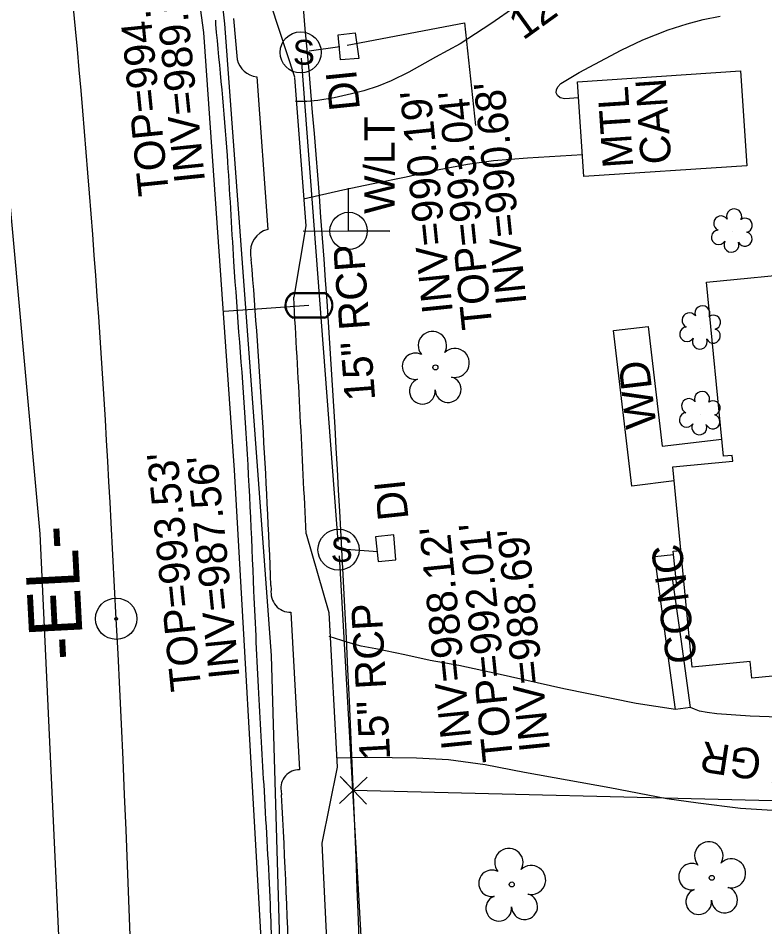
# Model space of a CAD drawing. Extents: x 1614611 to 1617571, y 898867 to 905462.
# Drawn here: x 1616674.8 to 1616772.7, y 902317.5 to 902436.7 of the extents above; entities that cross this region are included whole.
import ezdxf

# ---------------------------------------------------------------- set-up
doc = ezdxf.new("R2010")
doc.units = 0
for name, color, linetype in [('Exist Boundary Watershed Residential C 05', 7, 'Continuous'), ('Exist Building', 7, 'Continuous'), ('Exist Building Metal Canopy', 7, 'Continuous'), ('Exist Building Text', 7, 'Continuous'), ('Exist Horizontal Alignment Tick Label', 7, 'Continuous'), ('Exist Other Culture Area Outline', 7, 'Continuous'), ('Exist Roads Soil', 7, 'Continuous'), ('Exist Roads Soil Text', 7, 'Continuous'), ('Exist Structure Minor Drop Inlet Top Elevation', 7, 'Continuous'), ('Exist Structure Minor Pipes RCP 15 Inch Invert', 7, 'Continuous'), ('Exist Structure Minor Storm Sewer Manhole Top Elevation', 7, 'Continuous'), ('Exist Survey Centerline Point CELL', 7, 'Continuous'), ('Exist Utilities Power Joint Use Telephone CELL', 7, 'Continuous'), ('Exist Utilities Power Joint Use Telephone Text', 7, 'Continuous'), ('Exist Utilities Telephone UG Cable SUE LOS B', 7, 'Continuous'), ('Exist Utilities Telephone UG FO SUE LOS B', 7, 'Continuous'), ('Exist Utilities Water UG Line SUE LOS B', 7, 'Continuous'), ('Exist Vegetation Shrub CELL', 7, 'Continuous'), ('Exist Vegetation Tree CELL', 7, 'Continuous'), ('Prop Drainage Structure Catch Basin Adjust CELL', 7, 'Continuous'), ('Prop Drainage Structure Catch Basin Adjust Label', 7, 'Continuous'), ('Prop Drainage Structure Pipe Alternate 30in Label', 7, 'Continuous'), ('Prop Drainage Structure Pipe RCP 15in Class IV', 7, 'Continuous'), ('Prop Drainage Structure Tops and Inverts LABEL', 7, 'Continuous'), ('Prop Earthen Structure Head Ditch Label', 7, 'Continuous'), ('Prop Erosion Embankment Toe Protection CELL', 7, 'Continuous'), ('Prop Erosion Embankment Toe Protection with Rip Rap 2 Detail CELL', 7, 'Continuous'), ('Prop Plan Preparation Table Ditch Data CELL', 7, 'Continuous'), ('Prop SS Transition Line', 7, 'Continuous'), ('Raster_Level_2', 7, 'Continuous'), ('Raster_Level_3', 7, 'Continuous'), ('Scratch_Level_1', 7, 'Continuous'), ('Scratch_Level_9', 7, 'Continuous')]:
    doc.layers.add(name, color=color, linetype=linetype)

# ---------------------------------------------------------------- blocks, each defined once
blk = doc.blocks.new('EXIST STRUCTURE MINOR STORM SEWER MANHOLE')
at = {"layer": 'Prop Drainage Structure Pipe RCP 15in Class IV'}
blk.add_circle((0, 0), 0.0539, dxfattribs=at)
blk.add_text('S', height=0.065, dxfattribs=at).set_placement((-0.0206, -0.032))
blk = doc.blocks.new('EXIST SURVEY CENTERLINE POINT')
at = {"layer": 'Exist Survey Centerline Point CELL'}
for radius in [0.0542, 0.00375]:
    blk.add_circle((0, 0), radius, dxfattribs=at)
blk = doc.blocks.new('EXIST UTILITIES WATER METER')
at = {"layer": 'Prop SS Transition Line'}
blk.add_line((0, 0), (0, 0), dxfattribs=at)
for points in [[(-0.0408, 0.034), (0.0408, 0.034)], [(-0.0408, 0.0312), (0.0408, 0.0312)], [(0.0408, -0.0312), (-0.0413, -0.0312)], [(0.0408, -0.034), (-0.0413, -0.034)]]:
    blk.add_lwpolyline(points, dxfattribs=at)
for centre, radius, start, end in [((-0.0261, -0.0001), 0.0371, 113.178, 245.9794), ((-0.0259, -0.0001), 0.0347, 115.3009, 243.7824), ((0.0259, 0), 0.0371, 293.6483, 66.3084), ((0.0261, 0), 0.0345, 295.1272, 64.8728)]:
    blk.add_arc(centre, radius, start, end, dxfattribs=at)

msp = doc.modelspace()

# ---------------------------------------------------------------- linework, layer by layer
at = {"layer": 'Exist Boundary Watershed Residential C 05'}
for p, q in [((1616703.02, 902436.7), (1616703.51, 902431.31)), ((1616706.07, 902429.04), (1616707.51, 902409.02)), ((1616705.26, 902405.59), (1616705.35, 902405.07)), ((1616707.94, 902362.29), (1616707.97, 902361.76)), ((1616710.56, 902358.78), (1616711.7, 902338.11)), ((1616709.26, 902335.35), (1616709.32, 902334.83))]:
    msp.add_line(p, q, dxfattribs=at)
for centre, major_axis, ratio, start_param, end_param in [((1616706.37, 902431.96), (1.8, -2.32), 0.998961, 4.276319, 5.52203), ((1616708.3, 902406.05), (-2.36, -1.96), 0.999574, 4.277693, 5.74022), ((1615768.72, 902322.44), (-16.72, 991.07), 0.94837, 4.736603, 4.779853), ((1616710.53, 902361.37), (-2.59, -0.03), 0.999169, 6.117366, 7.854895), ((1616711.61, 902335.73), (-0.28, 2.37), 0.99892, 6.126992, 7.894157), ((1615570.16, 902271.61), (318.56, 1096.57), 0.999023, 5.027905, 5.050255)]:
    msp.add_ellipse(centre, major_axis=major_axis, ratio=ratio, start_param=start_param, end_param=end_param, dxfattribs=at)
at = {"layer": 'Exist Building'}
msp.add_lwpolyline([(1616804.86, 902353.42), (1616771, 902350.14), (1616770.79, 902352.34), (1616763.17, 902351.6), (1616760.63, 902377.86), (1616768.51, 902378.62), (1616768.43, 902379.37), (1616767.27, 902379.26), (1616765.05, 902402.11), (1616791.89, 902404.71), (1616793.95, 902383.49), (1616801.8, 902384.25), (1616801.98, 902382.41), (1616804.86, 902382.69), (1616807.23, 902358.2), (1616804.42, 902357.93)], close=True, dxfattribs=at)
at = {"layer": 'Exist Building Metal Canopy'}
msp.add_lwpolyline([(1616770.33, 902417.36), (1616748.96, 902415.94), (1616748.13, 902428.39), (1616769.49, 902429.82)], close=True, dxfattribs=at)
at = {"layer": 'Exist Other Culture Area Outline'}
for points in [[(1616760.8, 902376.01), (1616755.27, 902375.35), (1616752.85, 902395.74), (1616757.38, 902396.28), (1616759.25, 902380.58), (1616767.05, 902381.51)], [(1616762.09, 902362.73), (1616761.09, 902362.63), (1616760.66, 902366.81), (1616761.69, 902366.91)], [(1616762.96, 902346.3), (1616760.99, 902346.03), (1616759.76, 902354.99), (1616758.26, 902366.1), (1616760.71, 902366.38)], [(1616762.96, 902346.3), (1616761.73, 902355.26), (1616760.6, 902363.25), (1616761.03, 902363.3)]]:
    msp.add_lwpolyline(points, dxfattribs=at)
at = {"layer": 'Exist Roads Soil'}
for points in [[(1616740.04, 902438.27), (1616736.78, 902435.97), (1616732.75, 902433.37), (1616729.53, 902431.61), (1616726.01, 902429.65), (1616723.71, 902428.5), (1616721.99, 902427.79), (1616720.13, 902427.2), (1616718.5, 902426.78), (1616716.24, 902426.26), (1616714.08, 902425.92), (1616712.64, 902425.8), (1616711.16, 902425.81)], [(1616748.27, 902426.26), (1616746.49, 902426.15), (1616745.85, 902426.28), (1616745.5, 902426.57), (1616745.35, 902426.93), (1616745.36, 902427.33), (1616745.53, 902427.7), (1616745.94, 902428.14), (1616748.37, 902429.59), (1616753.87, 902432.51), (1616756.7, 902433.89), (1616760, 902435.21), (1616762.5, 902436), (1616764.6, 902436.55), (1616766.85, 902436.99)], [(1616712.2, 902413.04), (1616717.37, 902414.22), (1616721.34, 902415.04), (1616725.66, 902415.9), (1616729.29, 902416.73), (1616733.69, 902417.58), (1616737.11, 902418.06), (1616741.59, 902418.41), (1616748.77, 902418.82)], [(1616760.99, 902346.03), (1616755.84, 902346.82), (1616746.33, 902348.75), (1616737.61, 902350.7), (1616732.59, 902351.81), (1616728.83, 902352.48), (1616725.47, 902353.21), (1616721.68, 902353.97), (1616719.78, 902354.36), (1616718.07, 902354.83), (1616715.56, 902355.62)], [(1616776.96, 902344.94), (1616770.75, 902345.16), (1616766.39, 902345.45), (1616765.12, 902345.63), (1616764.14, 902345.83), (1616763.48, 902346.07), (1616762.96, 902346.3)], [(1616716.51, 902339.71), (1616720.63, 902339.78), (1616727, 902339.71), (1616731.2, 902339.48), (1616736.04, 902338.81), (1616741.16, 902337.82), (1616752.36, 902335.79), (1616759.83, 902334.37), (1616763.96, 902333.8), (1616769.5, 902333.1), (1616775.11, 902332.75)]]:
    msp.add_lwpolyline(points, dxfattribs=at)
at = {"layer": 'Exist Utilities Power Joint Use Telephone CELL'}
msp.add_line((1616718.12, 902408.81), (1616718.12, 902408.81), dxfattribs=at)
msp.add_lwpolyline([(1616712.18, 902408.81), (1616723.52, 902408.77), (1616718.12, 902408.79), (1616718.12, 902414.43)], dxfattribs=at)
msp.add_circle((1616718.12, 902408.81), 2.45, dxfattribs=at)
at = {"layer": 'Exist Utilities Telephone UG Cable SUE LOS B'}
msp.add_lwpolyline([(1616656.18, 902051.21), (1616671.87, 902049.35), (1616673.37, 902060.47), (1616677.62, 902099.17), (1616679.56, 902131), (1616682.04, 902274.91), (1616677.66, 902369.06), (1616673.54, 902414.87), (1616672.97, 902415.98), (1616670.64, 902416.97), (1616666.17, 902416.66), (1616663.13, 902416.28), (1616653.85, 902415.38)], dxfattribs=at)
at = {"layer": 'Exist Utilities Telephone UG FO SUE LOS B'}
msp.add_lwpolyline([(1616708.77, 902097.06), (1616709.58, 902140.25), (1616710.58, 902218.49), (1616710.01, 902283.99), (1616708.01, 902353.12), (1616701.91, 902435.97), (1616696.63, 902483.57), (1616691.69, 902526.33), (1616686.21, 902567.93), (1616679.63, 902610.92), (1616669.49, 902655.34), (1616656.06, 902717.52), (1616648.63, 902743.65), (1616630.5, 902815.16), (1616628.69, 902826.2), (1616634.94, 902830.28)], dxfattribs=at)
at = {"layer": 'Exist Utilities Water UG Line SUE LOS B'}
msp.add_line((1616712.92, 902399.05), (1616701.8, 902398.26), dxfattribs=at)
msp.add_lwpolyline([(1616682.85, 901889.35), (1616688.26, 901932.45), (1616696.61, 902016.19), (1616699.26, 902055.42), (1616702.78, 902110.39), (1616705.34, 902181.72), (1616707.31, 902255.35), (1616706.62, 902316.75), (1616703.14, 902377.45), (1616699.12, 902434.84), (1616686.86, 902524.85), (1616669.78, 902622.34), (1616658.13, 902681.62), (1616634.87, 902784.56), (1616617.17, 902853.52), (1616602.15, 902900.61), (1616584.28, 902954.24), (1616571.86, 902993.81)], dxfattribs=at)
at = {"layer": 'Exist Vegetation Shrub CELL'}
for p, q in [((1616768.44, 902408.68), (1616768.44, 902408.68)), ((1616764.29, 902395.96), (1616764.29, 902395.96)), ((1616764.23, 902384.72), (1616764.23, 902384.72))]:
    msp.add_line(p, q, dxfattribs=at)
for centre, radius, start, end in [((1616766.96, 902409.81), 0.968, 35.8908, 245.4216), ((1616768.67, 902410.72), 0.99, 334.8391, 200.4717), ((1616770.12, 902409.55), 0.929, 284.4567, 126.0861), ((1616766.64, 902407.98), 0.955, 95.1099, 327.9534), ((1616770.08, 902407.75), 0.937, 204.9913, 73.4601), ((1616768.32, 902407), 0.984, 151.2797, 21.387), ((1616764.51, 902398), 0.99, 334.8391, 200.4717), ((1616762.8, 902397.09), 0.968, 35.8908, 245.4216), ((1616765.96, 902396.83), 0.929, 284.4567, 126.0861), ((1616762.49, 902395.26), 0.955, 95.1099, 327.9534), ((1616765.92, 902395.03), 0.937, 204.9913, 73.4601), ((1616764.16, 902394.28), 0.984, 151.2797, 21.387), ((1616762.75, 902385.85), 0.968, 35.8908, 245.4216), ((1616764.46, 902386.76), 0.99, 334.8391, 200.4717), ((1616765.9, 902385.59), 0.929, 284.4567, 126.0861), ((1616762.43, 902384.02), 0.955, 95.1099, 327.9534), ((1616765.87, 902383.79), 0.937, 204.9913, 73.4601), ((1616764.1, 902383.04), 0.984, 151.2797, 21.387)]:
    msp.add_arc(centre, radius, start, end, dxfattribs=at)
at = {"layer": 'Exist Vegetation Tree CELL'}
for p, q in [((1616729.5, 902390.91), (1616729.5, 902390.91)), ((1616765.73, 902323.95), (1616765.73, 902323.95)), ((1616739.51, 902323.08), (1616739.51, 902323.08))]:
    msp.add_line(p, q, dxfattribs=at)
for centre in [(1616729.5, 902390.91), (1616765.73, 902323.95), (1616739.51, 902323.08)]:
    msp.add_circle(centre, 0.326, dxfattribs=at)
for centre, radius, start, end in [((1616729.11, 902393.78), 1.86, 330.1651, 219.7134), ((1616726.89, 902391.06), 1.73, 62.6636, 279.3457), ((1616732.05, 902391.5), 1.9, 257.1011, 134.1999), ((1616727.79, 902387.79), 1.69, 111.5671, 6.231), ((1616731.17, 902388.01), 1.7, 181.2822, 74.56), ((1616765.35, 902326.82), 1.86, 330.1651, 219.7134), ((1616739.13, 902325.95), 1.86, 330.1651, 219.7134), ((1616768.28, 902324.54), 1.9, 257.1011, 134.1999), ((1616736.91, 902323.23), 1.73, 62.6636, 279.3457), ((1616742.06, 902323.67), 1.9, 257.1011, 134.1999), ((1616763.13, 902324.1), 1.73, 62.6636, 279.3457), ((1616764.03, 902320.83), 1.69, 111.5671, 6.231), ((1616767.41, 902321.05), 1.7, 181.2822, 74.56), ((1616737.81, 902319.96), 1.69, 111.5671, 6.231), ((1616741.19, 902320.18), 1.7, 181.2822, 74.56)]:
    msp.add_arc(centre, radius, start, end, dxfattribs=at)
at = {"layer": 'Prop Drainage Structure Pipe Alternate 30in Label'}
msp.add_line((1616718.75, 902335.44), (1616926.32, 902330.37), dxfattribs=at)
at = {"layer": 'Prop Drainage Structure Tops and Inverts LABEL'}
msp.add_line((1616718.75, 902335.44), (1616718.75, 902335.44), dxfattribs=at)
msp.add_lwpolyline([(1616716.94, 902333.72), (1616720.56, 902337.17), (1616718.75, 902335.44), (1616717.02, 902337.25), (1616720.47, 902333.63)], dxfattribs=at)
at = {"layer": 'Prop Earthen Structure Head Ditch Label'}
msp.add_line((1616717.61, 902359.5), (1616716.96, 902372.07), dxfattribs=at)
for centre, radius, start, end in [((1615052.19, 902285.31), 1667.02, 2.98333, 9.05), ((1614235.45, 902230.14), 2485.53, 356.91518, 2.98333)]:
    msp.add_arc(centre, radius, start, end, dxfattribs=at)
at = {"layer": 'Prop Erosion Embankment Toe Protection CELL'}
for points in [[(1616716.73, 902434.55), (1616718.99, 902434.78), (1616719.45, 902431.44), (1616717.06, 902431.24), (1616716.73, 902434.55)], [(1616722, 902365.43), (1616724.3, 902365.68), (1616724.04, 902368.96), (1616721.65, 902368.69), (1616722, 902365.43)]]:
    msp.add_lwpolyline(points, dxfattribs=at)
at = {"layer": 'Prop Plan Preparation Table Ditch Data CELL'}
for p, q in [((1616712.95, 902432.45), (1616716.95, 902433)), ((1616711.91, 902431.48), (1616716.71, 902368.05)), ((1616717.79, 902367.07), (1616721.93, 902366.78)), ((1616716.87, 902366.19), (1616720.08, 902309.68))]:
    msp.add_line(p, q, dxfattribs=at)
at = {"layer": 'Raster_Level_2'}
msp.add_line((1616687.65, 902357.94), (1616687, 902370.51), dxfattribs=at)
for centre, radius, start, end in [((1615052.19, 902285.31), 1637.02, 2.98333, 9.05), ((1614235.45, 902230.14), 2455.53, 356.08333, 2.98333)]:
    msp.add_arc(centre, radius, start, end, dxfattribs=at)
at = {"layer": 'Raster_Level_3'}
msp.add_lwpolyline([(1616717.94, 902433.18), (1616733.3, 902436.1), (1616734.74, 902422.65)], dxfattribs=at)
at = {"layer": 'Scratch_Level_1'}
msp.add_line((1616707.92, 902438.46), (1616711.01, 902429.04), dxfattribs=at)
for points in [[(1616711.03, 902428.94), (1616712.5, 902409.5), (1616710.93, 902400.13)], [(1616712.55, 902369.06), (1616715.51, 902358.74), (1616716.6, 902338.47), (1616714.62, 902328.49), (1616715.21, 902315.8), (1616718.08, 902305.92), (1616718.43, 902285.38), (1616716.14, 902275.65)]]:
    msp.add_lwpolyline(points, dxfattribs=at)
msp.add_ellipse((1614231.79, 902241.59), major_axis=(-29.92, 2644.12), ratio=0.939305, start_param=4.749984, end_param=4.761751, dxfattribs=at)
at = {"layer": 'Scratch_Level_9'}
msp.add_line((1616700.67, 902436.46), (1616700.66, 902435.94), dxfattribs=at)
msp.add_spline([(1616700.66, 902435.94), (1616702.18, 902418.73), (1616703.04, 902404.79), (1616704.57, 902383.66), (1616705.67, 902361.58), (1616706.31, 902348.15), (1616707.03, 902335.33), (1616707.82, 902320.47), (1616708.2, 902308.47), (1616708.4, 902295.6), (1616708.73, 902282.72), (1616709.32, 902240.78), (1616708.76, 902198.62), (1616708, 902154.76), (1616706.39, 902118.44)], degree=3, dxfattribs=at)

# ---------------------------------------------------------------- block references
at = {"layer": 'Exist Horizontal Alignment Tick Label', "xscale": 50, "yscale": 50, "rotation": 1.7967031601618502e-12}
msp.add_blockref('EXIST SURVEY CENTERLINE POINT', (1616687.65, 902357.94), dxfattribs=at)
at = {"layer": 'Prop Drainage Structure Pipe RCP 15in Class IV', "xscale": 50, "yscale": 50}
for p in [(1616711.83, 902432.23), (1616716.8, 902367)]:
    msp.add_blockref('EXIST STRUCTURE MINOR STORM SEWER MANHOLE', p, dxfattribs=at)
at = {"layer": 'Prop SS Transition Line', "xscale": 50, "yscale": 50}
msp.add_blockref('EXIST UTILITIES WATER METER', (1616712.92, 902399.05), dxfattribs=at)

# ---------------------------------------------------------------- texts
at = {"layer": 'Exist Building Text'}
for s, rotation, p in [('CAN', 93.8148, (1616760.44, 902417.69)), ('MTL ', 93.8148, (1616755.45, 902417.2)), ('WD', 96.7806, (1616758.49, 902383.16)), ('CONC', 97.7191, (1616763.83, 902352.32))]:
    msp.add_text(s, height=4, rotation=rotation, dxfattribs=at).set_placement(p)
at = {"layer": 'Exist Roads Soil Text'}
for rotation, p in [(35.7973, (1616741, 902433.75)), (171.355, (1616780.83, 902339.4))]:
    msp.add_text("12' GR", height=4, rotation=rotation, dxfattribs=at).set_placement(p)
at = {"layer": 'Exist Structure Minor Drop Inlet Top Elevation'}
for s, p in [("TOP=993.04'", (1616736.98, 902396.08)), ("TOP=992.01'", (1616739.7, 902339.38))]:
    msp.add_text(s, height=4, rotation=95.8113, dxfattribs=at).set_placement(p)
at = {"layer": 'Exist Structure Minor Pipes RCP 15 Inch Invert'}
for s, p in [("INV=989.98'", (1616699.3, 902415.33)), ("INV=990.68'", (1616741.46, 902399.3)), ("INV=990.19'", (1616731.79, 902398.17)), ("INV=987.56'", (1616703.83, 902350.27)), ("INV=988.12'", (1616734.33, 902340.95)), ("INV=988.69'", (1616744.54, 902340.68))]:
    msp.add_text(s, height=4, rotation=95.8113, dxfattribs=at).set_placement(p)
at = {"layer": 'Exist Structure Minor Storm Sewer Manhole Top Elevation'}
for s, p in [("TOP=994.37'", (1616694.57, 902413.61)), ("TOP=993.53'", (1616698.82, 902348.62))]:
    msp.add_text(s, height=4, rotation=95.8113, dxfattribs=at).set_placement(p)
at = {"layer": 'Exist Utilities Power Joint Use Telephone Text'}
msp.add_text('W/LT', height=4, rotation=90, dxfattribs=at).set_placement((1616724.16, 902411.05))
at = {"layer": 'Prop Drainage Structure Catch Basin Adjust CELL'}
for rotation, p in [(95.8113, (1616719.62, 902424.78)), (96.0167, (1616725.99, 902371.05))]:
    msp.add_text('DI', height=4, rotation=rotation, dxfattribs=at).set_placement(p)
at = {"layer": 'Prop Drainage Structure Catch Basin Adjust Label'}
msp.add_text('-EL-', height=7, rotation=92.9833, dxfattribs=at).set_placement((1616683.4, 902352.66))
at = {"layer": 'Prop Erosion Embankment Toe Protection with Rip Rap 2 Detail CELL'}
for rotation, p in [(94.3276, (1616721.62, 902386.65)), (93.2513, (1616723.59, 902339.49))]:
    msp.add_text('15" RCP', height=4, rotation=rotation, dxfattribs=at).set_placement(p)

doc.saveas('drawing.dxf')
